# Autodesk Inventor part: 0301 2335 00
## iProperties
Shininess: 70.0
Length Units: 11269
Angle Units: 11279
Time Units: 11290
Mass Units: 11283
Length Display Precision: 3
Angle Display Precision: 2
Created: 2000-12
Part Number: 0301 2335 00
Material: Steel, Mild
Description: Washer
Document SubType Name: Modeling
Designer: Joe M
Engineer: Joe M
Density: 0.0
Volumn: 0.0
Area: 0.0
PropertySet Name: Model Information
Control State: 0
Master: False
Checked Out: False
Last Check In By: kodsd
Last Check In Date: 2002-01-07
Title: Bricka
Author: Joe M
